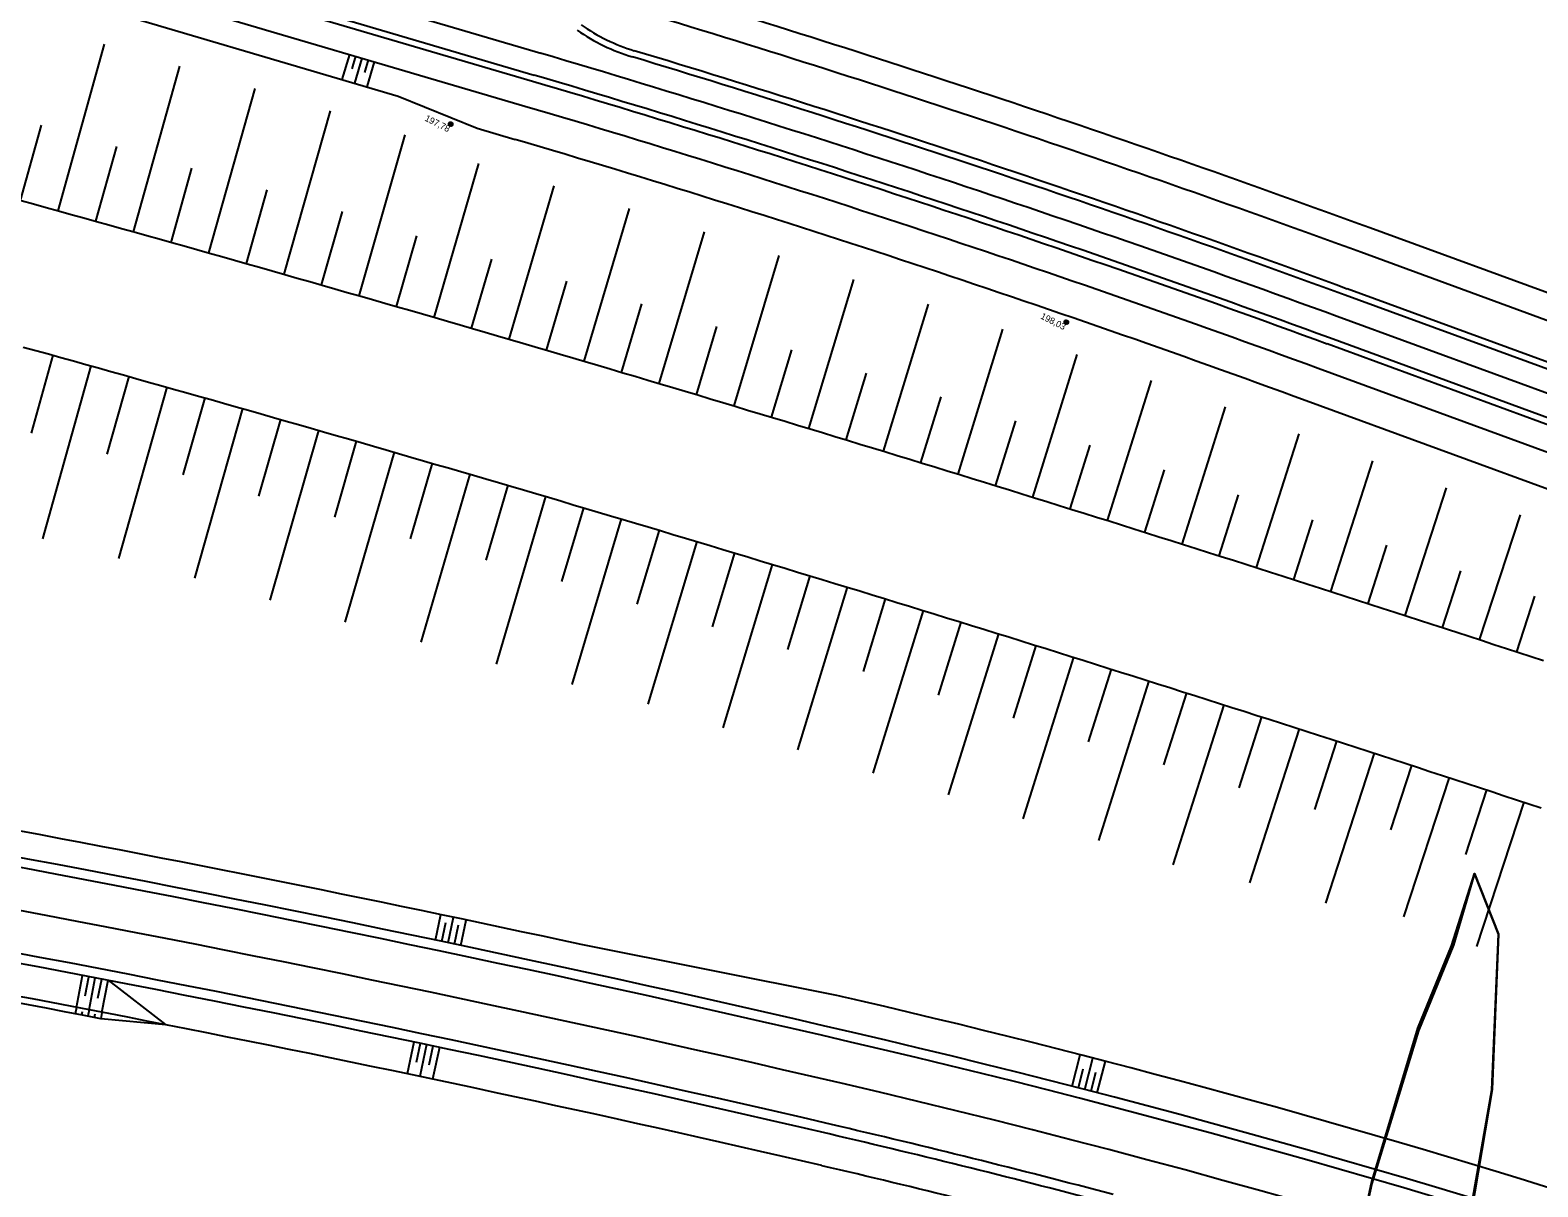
# Model space of a CAD drawing. Extents: x -552278 to -547230, y -1151007 to -1148251.
# Drawn here: x -550948.8 to -550833, y -1148819.7 to -1148730.8 of the extents above; entities that cross this region are included whole.
import ezdxf

# ---------------------------------------------------------------- set-up
doc = ezdxf.new("R2010")
doc.units = 0
for name, color, linetype in [('SO221815_VYSKOPIS', 7, 'Continuous'), ('u_IP17', 7, 'Continuous'), ('u_IP17_srafa', 7, 'Continuous'), ('u_STAVENIŠTĚ', 7, 'Continuous'), ('u_trat navrh', 7, 'Continuous')]:
    doc.layers.add(name, color=color, linetype=linetype)

# ---------------------------------------------------------------- blocks, each defined once
blk = doc.blocks.new('SO221824_VYSKOPIS')
at = {"layer": 'SO221815_VYSKOPIS'}
for p, q in [((1.2, -0.9), (-1.2, 0.9)), ((0.9, 1.2), (-0.9, -1.2)), ((0.9, 1.2), (0, 0)), ((0, 0), (1.2, -0.9))]:
    blk.add_line(p, q, dxfattribs=at)
blk.add_lwpolyline([(-0.9, -1.2), (0, 0), (-1.2, 0.9)], dxfattribs=at)
blk.add_circle((0, 0), 1.5, dxfattribs=at)
for start, end in [(145.362, 235.1538), (325.362, 55.1538)]:
    blk.add_arc((0, 0), 1.5, start, end, dxfattribs=at)

msp = doc.modelspace()

# ---------------------------------------------------------------- linework, layer by layer
at = {"layer": 'u_IP17'}
for points in [[(-550837.83, -1148795.62), (-550839.44, -1148801.11), (-550842.12, -1148807.69), (-550845.72, -1148819.42), (-550848.32, -1148831.42), (-550855.99, -1148876.44), (-550864.24, -1148922.29), (-550871.71, -1148953.2), (-550873.29, -1148961.31), (-550876.86, -1148984.92), (-550879.01, -1149003.49), (-550880.48, -1149016.26), (-550880.39, -1149028.48), (-550877.44, -1149050.4), (-550875.79, -1149066.52), (-550875.6, -1149089.61), (-550875.41, -1149112.7), (-550874.82, -1149156.2), (-550874.24, -1149199.69), (-550873.8, -1149233.1)], [(-550837.83, -1148795.62), (-550836, -1148800.28), (-550836.49, -1148812.22), (-550840.86, -1148837.25), (-550847.41, -1148874.18), (-550854.67, -1148916.87), (-550859.95, -1148946.62), (-550865.43, -1149000.99), (-550867.06, -1149034.41), (-550867.87, -1149048.76), (-550869.33, -1149071.89)]]:
    msp.add_lwpolyline(points, dxfattribs=at)
at = {"layer": 'u_IP17_srafa'}
msp.add_lwpolyline([(-550865.43, -1149000.99), (-550859.95, -1148946.62), (-550844.14, -1148855.72), (-550836.49, -1148812.22), (-550836, -1148800.28), (-550837.83, -1148795.62), (-550839.44, -1148801.11), (-550842.12, -1148807.69), (-550845.72, -1148819.42), (-550848.32, -1148831.42), (-550852.16, -1148853.93), (-550855.99, -1148876.44), (-550863.13, -1148916.53), (-550864.24, -1148922.29), (-550867.71, -1148936.4), (-550871.19, -1148950.5), (-550872.24, -1148955.91), (-550876.86, -1148984.92), (-550880.48, -1149016.26)], dxfattribs=at)
at = {"layer": 'u_STAVENIŠTĚ'}
msp.add_lwpolyline([(-550886.26, -1149014.34), (-550880.18, -1148968.42), (-550878.27, -1148955.49), (-550873.17, -1148934.79), (-550869.77, -1148921.11), (-550867.6, -1148909.22), (-550860.75, -1148871.36), (-550856.87, -1148848.79), (-550851.48, -1148849.7), (-550848.6, -1148833), (-550848.33, -1148831.4), (-550845.75, -1148819.38), (-550842.19, -1148807.49), (-550839.61, -1148801.16), (-550837.83, -1148795.62), (-550836, -1148800.28), (-550836.48, -1148812.21), (-550838.63, -1148824.91), (-550859.92, -1148946.62), (-550865.06, -1149001.1)], dxfattribs=at)
at = {"layer": 'u_trat navrh'}
for p, q in [((-550981.97, -1148711.25), (-550909.55, -1148732.61)), ((-550982.6, -1148713.4), (-550910.19, -1148734.77)), ((-550982.46, -1148712.92), (-550910.05, -1148734.29)), ((-550983.17, -1148715.32), (-550910.76, -1148736.69)), ((-550962.22, -1148723.59), (-550920.49, -1148735.9)), ((-550946.6, -1148744.72), (-550943.05, -1148731.91)), ((-550940.81, -1148746.33), (-550937.26, -1148733.62)), ((-550924.24, -1148732.71), (-550924.81, -1148734.63)), ((-550923.76, -1148732.85), (-550924.05, -1148733.81)), ((-550923.29, -1148732.99), (-550923.85, -1148734.91)), ((-550922.81, -1148733.13), (-550923.09, -1148734.09)), ((-550922.33, -1148733.28), (-550922.89, -1148735.19)), ((-550935.04, -1148747.95), (-550931.48, -1148735.33)), ((-550920.49, -1148735.9), (-550914.44, -1148738.36)), ((-550929.26, -1148749.59), (-550925.69, -1148737.04)), ((-550949.49, -1148743.92), (-550947.89, -1148738.13)), ((-550923.49, -1148751.24), (-550919.95, -1148738.89)), ((-550914.44, -1148738.36), (-550911.51, -1148739.23)), ((-550943.71, -1148745.52), (-550942.11, -1148739.78)), ((-550937.93, -1148747.14), (-550936.33, -1148741.44)), ((-550917.73, -1148752.9), (-550914.3, -1148741.08)), ((-550911.97, -1148754.58), (-550908.52, -1148742.79)), ((-550932.15, -1148748.77), (-550930.55, -1148743.1)), ((-550926.38, -1148750.41), (-550924.77, -1148744.78)), ((-550906.21, -1148756.27), (-550902.74, -1148744.54)), ((-550900.45, -1148757.98), (-550896.98, -1148746.32)), ((-550730.77, -1148788.22), (-550845.88, -1148746.02)), ((-550920.61, -1148752.07), (-550919.05, -1148746.65)), ((-550914.85, -1148753.74), (-550913.3, -1148748.43)), ((-550894.7, -1148759.7), (-550891.23, -1148748.14)), ((-550731.56, -1148790.07), (-550846.57, -1148747.9)), ((-550909.09, -1148755.43), (-550907.53, -1148750.13)), ((-550888.96, -1148761.43), (-550885.49, -1148749.99)), ((-550730, -1148793.83), (-550847.6, -1148750.72)), ((-550903.33, -1148757.13), (-550901.77, -1148751.86)), ((-550883.22, -1148763.18), (-550879.76, -1148751.88)), ((-550730.17, -1148794.3), (-550847.77, -1148751.19)), ((-550730.77, -1148795.94), (-550848.38, -1148752.83)), ((-550897.58, -1148758.84), (-550896.02, -1148753.61)), ((-550877.48, -1148764.94), (-550874.05, -1148753.8)), ((-550731.38, -1148797.59), (-550848.98, -1148754.47)), ((-550891.83, -1148760.57), (-550890.27, -1148755.39)), ((-550743.53, -1148793.66), (-550849.15, -1148754.94)), ((-550947.01, -1148755.81), (-550948.68, -1148761.8)), ((-550944.1, -1148756.62), (-550947.81, -1148769.9)), ((-550871.75, -1148766.72), (-550868.34, -1148755.76)), ((-550941.18, -1148757.44), (-550942.86, -1148763.41)), ((-550886.09, -1148762.31), (-550884.53, -1148757.19)), ((-550866.02, -1148768.51), (-550862.65, -1148757.75)), ((-550744.31, -1148795.51), (-550849.84, -1148756.82)), ((-550938.26, -1148758.26), (-550941.98, -1148771.43)), ((-550935.35, -1148759.09), (-550937.03, -1148765)), ((-550880.35, -1148764.06), (-550878.8, -1148759.01)), ((-550932.44, -1148759.91), (-550936.14, -1148772.93)), ((-550860.29, -1148770.31), (-550856.96, -1148759.78)), ((-550795.36, -1148779.62), (-550850.75, -1148759.31)), ((-550929.53, -1148760.74), (-550931.21, -1148766.64)), ((-550874.61, -1148765.83), (-550873.07, -1148760.85)), ((-550926.62, -1148761.58), (-550930.36, -1148774.62)), ((-550923.71, -1148762.42), (-550925.39, -1148768.26)), ((-550854.57, -1148772.12), (-550851.29, -1148761.84)), ((-550920.8, -1148763.26), (-550924.58, -1148776.32)), ((-550868.88, -1148767.61), (-550867.36, -1148762.72)), ((-550917.89, -1148764.1), (-550919.58, -1148769.9)), ((-550863.15, -1148769.41), (-550861.65, -1148764.61)), ((-550848.86, -1148773.95), (-550845.63, -1148763.91)), ((-550914.98, -1148764.95), (-550918.76, -1148777.86)), ((-550912.08, -1148765.8), (-550913.76, -1148771.55)), ((-550843.15, -1148775.8), (-550839.97, -1148765.99)), ((-550909.17, -1148766.66), (-550912.97, -1148779.54)), ((-550857.43, -1148771.22), (-550855.95, -1148766.53)), ((-550906.27, -1148767.52), (-550907.95, -1148773.18)), ((-550837.44, -1148777.66), (-550834.31, -1148768.06)), ((-550903.37, -1148768.38), (-550907.15, -1148781.09)), ((-550900.46, -1148769.25), (-550902.16, -1148774.93)), ((-550851.71, -1148773.04), (-550850.25, -1148768.46)), ((-550897.56, -1148770.12), (-550901.32, -1148782.61)), ((-550846, -1148774.87), (-550844.56, -1148770.41)), ((-550894.66, -1148770.99), (-550896.38, -1148776.68)), ((-550891.77, -1148771.87), (-550895.57, -1148784.44)), ((-550888.87, -1148772.75), (-550890.59, -1148778.4)), ((-550840.29, -1148776.72), (-550838.87, -1148772.36)), ((-550886.01, -1148773.62), (-550889.82, -1148786.11)), ((-550883.08, -1148774.52), (-550884.79, -1148780.09)), ((-550834.59, -1148778.59), (-550833.19, -1148774.32)), ((-550880.18, -1148775.41), (-550884.04, -1148787.91)), ((-550877.29, -1148776.31), (-550879.03, -1148781.91)), ((-550874.4, -1148777.2), (-550878.25, -1148789.58)), ((-550871.51, -1148778.1), (-550873.25, -1148783.69)), ((-550868.62, -1148779.01), (-550872.51, -1148791.42)), ((-550865.73, -1148779.92), (-550867.49, -1148785.49)), ((-550862.84, -1148780.83), (-550866.72, -1148793.08)), ((-550859.96, -1148781.75), (-550861.71, -1148787.27)), ((-550857.07, -1148782.66), (-550860.99, -1148794.96)), ((-550854.19, -1148783.59), (-550855.93, -1148789.04)), ((-550851.3, -1148784.51), (-550855.11, -1148796.34)), ((-550848.42, -1148785.44), (-550850.12, -1148790.69)), ((-550845.54, -1148786.38), (-550849.28, -1148797.89)), ((-550842.66, -1148787.31), (-550844.27, -1148792.25)), ((-550839.78, -1148788.25), (-550843.28, -1148798.95)), ((-550836.9, -1148789.2), (-550838.53, -1148794.15)), ((-550834.03, -1148790.14), (-550837.68, -1148801.23)), ((-550917.64, -1148800.73), (-550917.23, -1148798.77)), ((-550917.15, -1148800.83), (-550916.84, -1148799.37)), ((-550916.66, -1148800.94), (-550916.25, -1148798.98)), ((-550916.17, -1148801.04), (-550915.86, -1148799.57)), ((-550915.68, -1148801.14), (-550915.27, -1148799.19)), ((-550886.81, -1148804.98), (-550906.43, -1148801.08)), ((-550945.21, -1148805.9), (-550944.74, -1148803.45)), ((-550944.53, -1148805.01), (-550944.25, -1148803.54)), ((-550944.23, -1148806.09), (-550943.76, -1148803.63)), ((-550943.55, -1148805.2), (-550943.26, -1148803.73)), ((-550943.25, -1148806.28), (-550942.77, -1148803.82)), ((-550942.77, -1148803.82), (-550938.34, -1148807.24)), ((-550945.21, -1148805.9), (-550945.3, -1148806.39)), ((-550944.77, -1148806.24), (-550944.81, -1148806.49)), ((-550944.23, -1148806.09), (-550944.32, -1148806.58)), ((-550943.79, -1148806.43), (-550943.83, -1148806.68)), ((-550943.25, -1148806.28), (-550943.34, -1148806.77)), ((-550938.34, -1148807.24), (-550943.34, -1148806.77)), ((-550919.29, -1148808.56), (-550919.8, -1148811.01)), ((-550918.8, -1148808.66), (-550919.11, -1148810.13)), ((-550918.31, -1148808.76), (-550918.83, -1148811.21)), ((-550917.82, -1148808.87), (-550918.13, -1148810.34)), ((-550917.33, -1148808.97), (-550917.85, -1148811.42)), ((-550868.73, -1148811.96), (-550868.11, -1148809.54)), ((-550867.77, -1148812.21), (-550867.14, -1148809.79)), ((-550866.8, -1148812.46), (-550866.17, -1148810.04)), ((-550868.25, -1148812.08), (-550867.88, -1148810.63)), ((-550867.28, -1148812.33), (-550866.91, -1148810.88)), ((-550888.55, -1148811.25), (-550888.55, -1148811.25))]:
    msp.add_line(p, q, dxfattribs=at)
for points in [[(-550949.46, -1148743.93), (-550948.5, -1148744.19), (-550947.53, -1148744.46), (-550946.57, -1148744.73), (-550945.6, -1148744.99), (-550944.64, -1148745.26), (-550943.67, -1148745.53), (-550942.71, -1148745.8), (-550941.74, -1148746.07), (-550940.78, -1148746.34), (-550939.81, -1148746.61), (-550938.85, -1148746.88), (-550937.88, -1148747.15), (-550936.92, -1148747.42), (-550935.96, -1148747.69), (-550934.99, -1148747.96), (-550934.03, -1148748.23), (-550933.07, -1148748.51), (-550932.1, -1148748.78), (-550931.14, -1148749.05), (-550930.18, -1148749.33), (-550929.21, -1148749.6), (-550928.25, -1148749.88), (-550927.29, -1148750.15), (-550926.32, -1148750.43), (-550925.36, -1148750.7), (-550924.4, -1148750.98), (-550923.44, -1148751.25), (-550922.47, -1148751.53), (-550921.51, -1148751.81), (-550920.55, -1148752.09), (-550919.59, -1148752.36), (-550918.63, -1148752.64), (-550917.66, -1148752.92), (-550916.7, -1148753.2), (-550915.74, -1148753.48), (-550914.78, -1148753.76), (-550913.82, -1148754.04), (-550912.86, -1148754.32), (-550911.9, -1148754.6), (-550910.93, -1148754.88), (-550909.97, -1148755.17), (-550909.01, -1148755.45), (-550908.05, -1148755.73), (-550907.09, -1148756.01), (-550906.13, -1148756.3), (-550905.17, -1148756.58), (-550904.21, -1148756.86), (-550903.25, -1148757.15), (-550902.29, -1148757.43), (-550901.33, -1148757.72), (-550900.37, -1148758.01), (-550899.41, -1148758.29), (-550898.45, -1148758.58), (-550897.49, -1148758.86), (-550896.53, -1148759.15), (-550895.57, -1148759.44), (-550894.62, -1148759.73), (-550893.66, -1148760.02), (-550892.7, -1148760.3), (-550891.74, -1148760.59), (-550890.78, -1148760.88), (-550889.82, -1148761.17), (-550888.86, -1148761.46), (-550887.91, -1148761.75), (-550886.95, -1148762.04), (-550885.99, -1148762.34), (-550885.03, -1148762.63), (-550884.07, -1148762.92), (-550883.12, -1148763.21), (-550882.16, -1148763.51), (-550881.2, -1148763.8), (-550880.24, -1148764.09), (-550879.29, -1148764.39), (-550878.33, -1148764.68), (-550877.37, -1148764.98), (-550876.42, -1148765.27), (-550875.46, -1148765.57), (-550874.5, -1148765.86), (-550873.55, -1148766.16), (-550872.59, -1148766.46), (-550871.63, -1148766.75), (-550870.68, -1148767.05), (-550869.72, -1148767.35), (-550868.76, -1148767.65), (-550867.81, -1148767.95), (-550866.85, -1148768.24), (-550865.9, -1148768.54), (-550864.94, -1148768.84), (-550863.99, -1148769.14), (-550863.03, -1148769.44), (-550862.08, -1148769.75), (-550861.12, -1148770.05), (-550860.17, -1148770.35), (-550859.21, -1148770.65), (-550858.26, -1148770.95), (-550857.3, -1148771.26), (-550856.35, -1148771.56), (-550855.39, -1148771.86), (-550854.44, -1148772.17), (-550853.49, -1148772.47), (-550852.53, -1148772.78), (-550851.58, -1148773.08), (-550850.63, -1148773.39), (-550849.67, -1148773.69), (-550848.72, -1148774), (-550847.77, -1148774.31), (-550846.81, -1148774.61), (-550845.86, -1148774.92), (-550844.91, -1148775.23), (-550843.95, -1148775.54), (-550843, -1148775.84), (-550842.05, -1148776.15), (-550841.1, -1148776.46), (-550840.14, -1148776.77), (-550839.75, -1148776.9), (-550839.19, -1148777.08), (-550838.24, -1148777.39), (-550837.29, -1148777.7), (-550836.34, -1148778.02), (-550835.38, -1148778.33), (-550834.43, -1148778.64), (-550833.48, -1148778.95), (-550832.53, -1148779.26)], [(-550949.29, -1148755.18), (-550948.33, -1148755.45), (-550947.36, -1148755.71), (-550946.4, -1148755.98), (-550945.44, -1148756.25), (-550944.48, -1148756.52), (-550943.52, -1148756.79), (-550942.55, -1148757.06), (-550941.59, -1148757.32), (-550940.63, -1148757.59), (-550939.67, -1148757.87), (-550938.71, -1148758.14), (-550937.75, -1148758.41), (-550936.79, -1148758.68), (-550935.83, -1148758.95), (-550934.86, -1148759.22), (-550933.9, -1148759.5), (-550932.94, -1148759.77), (-550931.98, -1148760.04), (-550931.02, -1148760.32), (-550930.06, -1148760.59), (-550929.1, -1148760.87), (-550928.14, -1148761.14), (-550927.18, -1148761.42), (-550926.22, -1148761.69), (-550925.26, -1148761.97), (-550924.3, -1148762.24), (-550923.34, -1148762.52), (-550922.38, -1148762.8), (-550921.42, -1148763.08), (-550920.46, -1148763.35), (-550919.51, -1148763.63), (-550918.55, -1148763.91), (-550917.59, -1148764.19), (-550916.63, -1148764.47), (-550915.67, -1148764.75), (-550914.71, -1148765.03), (-550913.75, -1148765.31), (-550912.79, -1148765.59), (-550911.84, -1148765.87), (-550910.88, -1148766.16), (-550909.92, -1148766.44), (-550908.96, -1148766.72), (-550908.01, -1148767), (-550907.05, -1148767.29), (-550906.09, -1148767.57), (-550905.13, -1148767.86), (-550904.18, -1148768.14), (-550903.22, -1148768.43), (-550902.26, -1148768.71), (-550901.3, -1148769), (-550900.35, -1148769.28), (-550899.39, -1148769.57), (-550898.43, -1148769.86), (-550897.48, -1148770.14), (-550896.52, -1148770.43), (-550895.56, -1148770.72), (-550894.61, -1148771.01), (-550893.65, -1148771.3), (-550892.7, -1148771.59), (-550891.74, -1148771.88), (-550890.78, -1148772.17), (-550889.83, -1148772.46), (-550888.87, -1148772.75), (-550887.92, -1148773.04), (-550886.96, -1148773.33), (-550886.01, -1148773.62), (-550885.05, -1148773.91), (-550884.1, -1148774.21), (-550883.14, -1148774.5), (-550882.19, -1148774.79), (-550881.23, -1148775.09), (-550880.28, -1148775.38), (-550879.33, -1148775.68), (-550878.37, -1148775.97), (-550877.42, -1148776.27), (-550876.46, -1148776.56), (-550875.51, -1148776.86), (-550874.56, -1148777.15), (-550873.6, -1148777.45), (-550872.65, -1148777.75), (-550871.7, -1148778.05), (-550870.74, -1148778.34), (-550869.79, -1148778.64), (-550868.84, -1148778.94), (-550867.88, -1148779.24), (-550866.93, -1148779.54), (-550865.98, -1148779.84), (-550865.03, -1148780.14), (-550864.07, -1148780.44), (-550863.12, -1148780.74), (-550862.17, -1148781.04), (-550861.22, -1148781.34), (-550860.26, -1148781.65), (-550859.31, -1148781.95), (-550858.36, -1148782.25), (-550857.41, -1148782.56), (-550856.46, -1148782.86), (-550855.51, -1148783.16), (-550854.56, -1148783.47), (-550853.6, -1148783.77), (-550852.65, -1148784.08), (-550851.7, -1148784.38), (-550850.75, -1148784.69), (-550849.8, -1148785), (-550848.85, -1148785.3), (-550847.9, -1148785.61), (-550846.95, -1148785.92), (-550846, -1148786.23), (-550845.05, -1148786.53), (-550844.1, -1148786.84), (-550843.15, -1148787.15), (-550843.08, -1148787.17), (-550842.2, -1148787.46), (-550841.25, -1148787.77), (-550840.3, -1148788.08), (-550839.35, -1148788.39), (-550838.4, -1148788.7), (-550837.46, -1148789.01), (-550836.51, -1148789.33), (-550835.56, -1148789.64), (-550834.61, -1148789.95), (-550833.66, -1148790.26), (-550832.71, -1148790.58)]]:
    msp.add_lwpolyline(points, dxfattribs=at)
for centre, radius, start, end in [((-551192.58, -1149691.73), 1007.25, 69.86671, 73.16776), ((-551192.58, -1149691.73), 1005.25, 69.86671, 73.16776), ((-550898.16, -1148718.54), 15, 235.1241, 253.1678), ((-550898.16, -1148718.54), 14.5, 235.1241, 253.1678), ((-551192.58, -1149691.73), 1002.25, 69.86671, 73.16776), ((-551192.58, -1149691.73), 1000, 69.86671, 73.55904), ((-551192.58, -1149691.73), 1001.75, 69.86671, 73.16776), ((-551192.58, -1149691.73), 997.75, 69.86671, 73.55904), ((-551192.58, -1149691.73), 998.25, 69.86671, 73.55904), ((-551192.58, -1149691.73), 995.75, 69.86671, 73.55904), ((-551192.58, -1149691.73), 993.1, 69.86671, 73.55904), ((-551226.7, -1150272.63), 1503.25, 76.89047, 82.52854), ((-551226.7, -1150272.63), 1504, 76.89047, 82.52854), ((-551226.7, -1150272.63), 1506, 77.72157, 81.54129), ((-551226.7, -1150272.63), 1500, 76.89047, 82.52854), ((-551226.7, -1150272.63), 1496.75, 76.89047, 82.52854), ((-551226.7, -1150272.63), 1496, 76.89047, 82.52854), ((-551226.7, -1150272.63), 1493, 79.0593, 82.52854), ((-551226.7, -1150272.63), 1493.5, 78.86749, 82.52854), ((-551226.7, -1150272.63), 1506.5, 76.89047, 76.96092), ((-551056.59, -1149542.18), 756.5, 67.46341, 76.89047), ((-551226.7, -1150272.63), 1493.5, 76.89047, 78.86749), ((-551056.59, -1149542.18), 753.25, 51.79075, 76.89047), ((-551056.59, -1149542.18), 754, 51.79075, 76.89047), ((-551056.59, -1149542.18), 750, 47.42068, 76.89047), ((-551056.59, -1149542.18), 746, 75.17971, 76.89047), ((-551056.59, -1149542.18), 746.75, 75.17971, 76.89047), ((-551056.59, -1149542.18), 743.5, 75.17971, 76.89047)]:
    msp.add_arc(centre, radius, start, end, dxfattribs=at)

# ---------------------------------------------------------------- block references
at = {"layer": 'u_trat navrh', "xscale": 0.1, "yscale": 0.09999999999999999, "rotation": -31.851985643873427}
for p in [(-550916.46, -1148738.06), (-550869.18, -1148753.27)]:
    msp.add_blockref('SO221824_VYSKOPIS', p, dxfattribs=at)

# ---------------------------------------------------------------- texts
at = {"layer": 'u_trat navrh'}
for s, p in [('197,78', (-550918.5, -1148737.77)), ('198,03', (-550871.21, -1148752.97))]:
    msp.add_text(s, height=0.5, rotation=333.2568, dxfattribs=at).set_placement(p)

doc.saveas('drawing.dxf')
